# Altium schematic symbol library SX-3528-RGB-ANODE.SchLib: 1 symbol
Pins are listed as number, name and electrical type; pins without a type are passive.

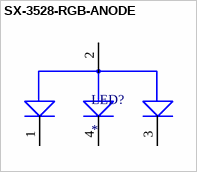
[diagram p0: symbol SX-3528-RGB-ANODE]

## SX-3528-RGB-ANODE
designator LED?
LED; SMD 3528, PLCC2; RGB; 3.5x2.8mm; 120Â°; RGB;   3.2-3.6V; MF: Lucky Light; MP: LL-R3528RGBC-008-B
footprint SX-3528-RGB-ANODE
pins: 1 CATHODE_RED, 2 ANODE, 3 CATHODE_BLUE, 4 CATHODE_GREEN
